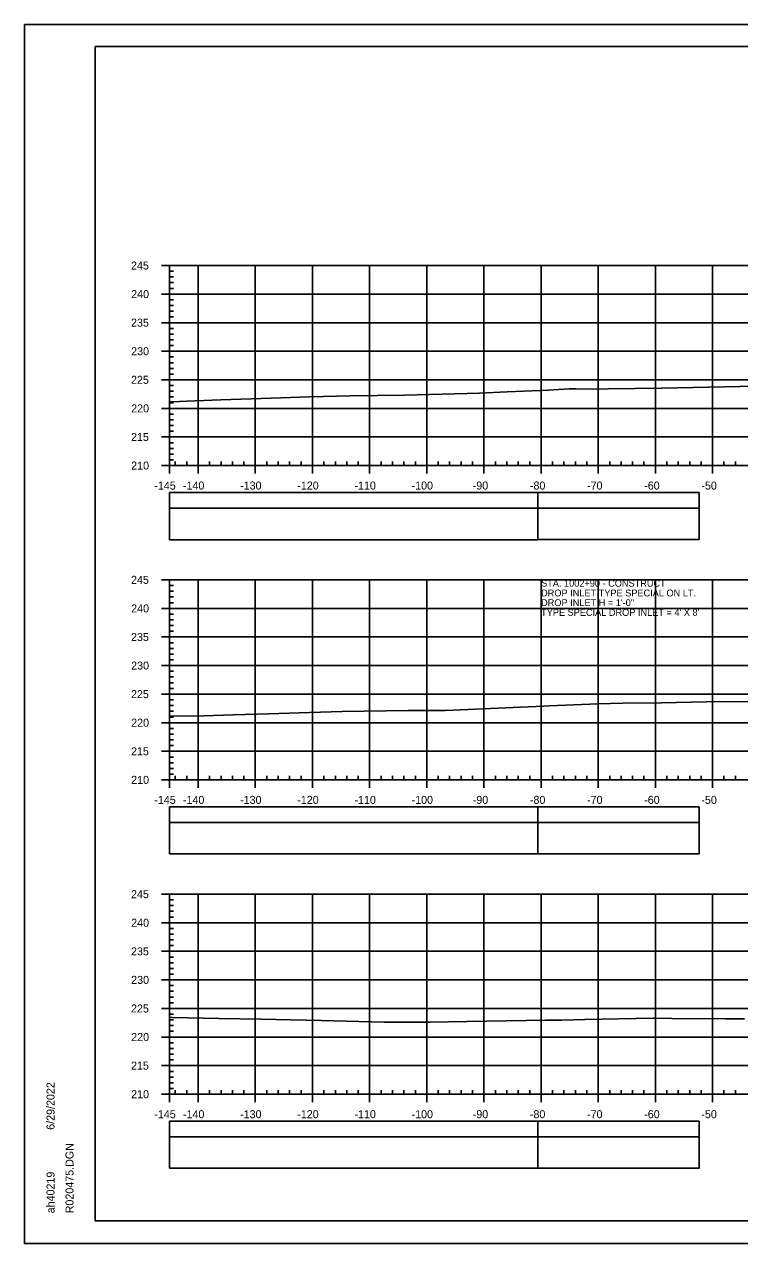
# Model space of a CAD drawing. Extents: x 1386544 to 1388153, y 379785 to 390999.
# Drawn here: x 1387207.5 to 1387332.7, y 379998.1 to 380211.5 of the extents above; entities that cross this region are included whole.
import ezdxf

# ---------------------------------------------------------------- set-up
doc = ezdxf.new("R2010")
doc.units = 0
for name, color, linetype in [('R_Axis', 7, 'Continuous'), ('R_Axis Annot', 7, 'Continuous'), ('R_Border', 7, 'Continuous'), ('R_Exist Surface', 7, 'Continuous'), ('R_Grid', 7, 'Continuous'), ('R_No Plot', 7, 'Continuous'), ('R_Striping', 7, 'Continuous'), ('R_Water Annot', 7, 'Continuous')]:
    doc.layers.add(name, color=color, linetype=linetype)

msp = doc.modelspace()

# ---------------------------------------------------------------- linework, layer by layer
at = {"layer": 'R_Axis'}
for p, q in [((1387231.55, 380169.28), (1387232.95, 380169.28)), ((1387232.95, 380134.28), (1387232.95, 380169.28)), ((1387232.95, 380168.28), (1387233.65, 380168.28)), ((1387232.95, 380167.28), (1387233.65, 380167.28)), ((1387232.95, 380166.28), (1387233.65, 380166.28)), ((1387231.55, 380164.28), (1387232.95, 380164.28)), ((1387232.95, 380165.28), (1387233.65, 380165.28)), ((1387232.95, 380163.28), (1387233.65, 380163.28)), ((1387232.95, 380162.28), (1387233.65, 380162.28)), ((1387232.95, 380161.28), (1387233.65, 380161.28)), ((1387231.55, 380159.28), (1387232.95, 380159.28)), ((1387232.95, 380160.28), (1387233.65, 380160.28)), ((1387232.95, 380158.28), (1387233.65, 380158.28)), ((1387232.95, 380157.28), (1387233.65, 380157.28)), ((1387232.95, 380156.28), (1387233.65, 380156.28)), ((1387232.95, 380155.28), (1387233.65, 380155.28)), ((1387231.55, 380154.28), (1387232.95, 380154.28)), ((1387232.95, 380153.28), (1387233.65, 380153.28)), ((1387232.95, 380152.28), (1387233.65, 380152.28)), ((1387232.95, 380151.28), (1387233.65, 380151.28)), ((1387231.55, 380149.28), (1387232.95, 380149.28)), ((1387232.95, 380150.28), (1387233.65, 380150.28)), ((1387232.95, 380148.28), (1387233.65, 380148.28)), ((1387232.95, 380147.28), (1387233.65, 380147.28)), ((1387232.95, 380146.28), (1387233.65, 380146.28)), ((1387231.55, 380144.28), (1387232.95, 380144.28)), ((1387232.95, 380145.28), (1387233.65, 380145.28)), ((1387232.95, 380143.28), (1387233.65, 380143.28)), ((1387232.95, 380142.28), (1387233.65, 380142.28)), ((1387232.95, 380141.28), (1387233.65, 380141.28)), ((1387232.95, 380140.28), (1387233.65, 380140.28)), ((1387231.55, 380139.28), (1387232.95, 380139.28)), ((1387232.95, 380138.28), (1387233.65, 380138.28)), ((1387232.95, 380137.28), (1387233.65, 380137.28)), ((1387232.95, 380136.28), (1387233.65, 380136.28)), ((1387231.55, 380134.28), (1387232.95, 380134.28)), ((1387232.95, 380135.28), (1387233.65, 380135.28)), ((1387232.95, 380134.28), (1387232.95, 380134.98)), ((1387232.95, 380134.28), (1387522.95, 380134.28)), ((1387232.95, 380132.88), (1387232.95, 380134.28)), ((1387233.95, 380134.28), (1387233.95, 380134.98)), ((1387235.95, 380134.28), (1387235.95, 380134.98)), ((1387237.95, 380132.88), (1387237.95, 380134.28)), ((1387239.95, 380134.28), (1387239.95, 380134.98)), ((1387241.95, 380134.28), (1387241.95, 380134.98)), ((1387243.95, 380134.28), (1387243.95, 380134.98)), ((1387245.95, 380134.28), (1387245.95, 380134.98)), ((1387247.95, 380132.88), (1387247.95, 380134.28)), ((1387249.95, 380134.28), (1387249.95, 380134.98)), ((1387251.95, 380134.28), (1387251.95, 380134.98)), ((1387253.95, 380134.28), (1387253.95, 380134.98)), ((1387255.95, 380134.28), (1387255.95, 380134.98)), ((1387257.95, 380132.88), (1387257.95, 380134.28)), ((1387259.95, 380134.28), (1387259.95, 380134.98)), ((1387261.95, 380134.28), (1387261.95, 380134.98)), ((1387263.95, 380134.28), (1387263.95, 380134.98)), ((1387265.95, 380134.28), (1387265.95, 380134.98)), ((1387267.95, 380132.88), (1387267.95, 380134.28)), ((1387269.95, 380134.28), (1387269.95, 380134.98)), ((1387271.95, 380134.28), (1387271.95, 380134.98)), ((1387273.95, 380134.28), (1387273.95, 380134.98)), ((1387275.95, 380134.28), (1387275.95, 380134.98)), ((1387277.95, 380132.88), (1387277.95, 380134.28)), ((1387279.95, 380134.28), (1387279.95, 380134.98)), ((1387281.95, 380134.28), (1387281.95, 380134.98)), ((1387283.95, 380134.28), (1387283.95, 380134.98)), ((1387285.95, 380134.28), (1387285.95, 380134.98)), ((1387287.95, 380132.88), (1387287.95, 380134.28)), ((1387289.95, 380134.28), (1387289.95, 380134.98)), ((1387291.95, 380134.28), (1387291.95, 380134.98)), ((1387293.95, 380134.28), (1387293.95, 380134.98)), ((1387295.95, 380134.28), (1387295.95, 380134.98)), ((1387297.95, 380132.88), (1387297.95, 380134.28)), ((1387299.95, 380134.28), (1387299.95, 380134.98)), ((1387301.95, 380134.28), (1387301.95, 380134.98)), ((1387303.95, 380134.28), (1387303.95, 380134.98)), ((1387305.95, 380134.28), (1387305.95, 380134.98)), ((1387307.95, 380132.88), (1387307.95, 380134.28)), ((1387309.95, 380134.28), (1387309.95, 380134.98)), ((1387311.95, 380134.28), (1387311.95, 380134.98)), ((1387313.95, 380134.28), (1387313.95, 380134.98)), ((1387315.95, 380134.28), (1387315.95, 380134.98)), ((1387317.95, 380132.88), (1387317.95, 380134.28)), ((1387319.95, 380134.28), (1387319.95, 380134.98)), ((1387321.95, 380134.28), (1387321.95, 380134.98)), ((1387323.95, 380134.28), (1387323.95, 380134.98)), ((1387325.95, 380134.28), (1387325.95, 380134.98)), ((1387327.95, 380132.88), (1387327.95, 380134.28)), ((1387329.95, 380134.28), (1387329.95, 380134.98)), ((1387331.95, 380134.28), (1387331.95, 380134.98)), ((1387231.55, 380114.28), (1387232.95, 380114.28)), ((1387232.95, 380079.28), (1387232.95, 380114.28)), ((1387232.95, 380113.28), (1387233.65, 380113.28)), ((1387232.95, 380112.28), (1387233.65, 380112.28)), ((1387232.95, 380111.28), (1387233.65, 380111.28)), ((1387232.95, 380110.28), (1387233.65, 380110.28)), ((1387231.55, 380109.28), (1387232.95, 380109.28)), ((1387232.95, 380108.28), (1387233.65, 380108.28)), ((1387232.95, 380107.28), (1387233.65, 380107.28)), ((1387232.95, 380106.28), (1387233.65, 380106.28)), ((1387231.55, 380104.28), (1387232.95, 380104.28)), ((1387232.95, 380105.28), (1387233.65, 380105.28)), ((1387232.95, 380103.28), (1387233.65, 380103.28)), ((1387232.95, 380102.28), (1387233.65, 380102.28)), ((1387232.95, 380101.28), (1387233.65, 380101.28)), ((1387232.95, 380100.28), (1387233.65, 380100.28)), ((1387231.55, 380099.28), (1387232.95, 380099.28)), ((1387232.95, 380098.28), (1387233.65, 380098.28)), ((1387232.95, 380097.28), (1387233.65, 380097.28)), ((1387232.95, 380096.28), (1387233.65, 380096.28)), ((1387232.95, 380095.28), (1387233.65, 380095.28)), ((1387231.55, 380094.28), (1387232.95, 380094.28)), ((1387232.95, 380093.28), (1387233.65, 380093.28)), ((1387232.95, 380092.28), (1387233.65, 380092.28)), ((1387232.95, 380091.28), (1387233.65, 380091.28)), ((1387231.55, 380089.28), (1387232.95, 380089.28)), ((1387232.95, 380090.28), (1387233.65, 380090.28)), ((1387232.95, 380088.28), (1387233.65, 380088.28)), ((1387232.95, 380087.28), (1387233.65, 380087.28)), ((1387232.95, 380086.28), (1387233.65, 380086.28)), ((1387232.95, 380085.28), (1387233.65, 380085.28)), ((1387231.55, 380084.28), (1387232.95, 380084.28)), ((1387232.95, 380083.28), (1387233.65, 380083.28)), ((1387232.95, 380082.28), (1387233.65, 380082.28)), ((1387232.95, 380081.28), (1387233.65, 380081.28)), ((1387232.95, 380080.28), (1387233.65, 380080.28)), ((1387231.55, 380079.28), (1387232.95, 380079.28)), ((1387232.95, 380079.28), (1387232.95, 380079.98)), ((1387232.95, 380079.28), (1387522.95, 380079.28)), ((1387232.95, 380077.88), (1387232.95, 380079.28)), ((1387233.95, 380079.28), (1387233.95, 380079.98)), ((1387235.95, 380079.28), (1387235.95, 380079.98)), ((1387237.95, 380077.88), (1387237.95, 380079.28)), ((1387239.95, 380079.28), (1387239.95, 380079.98)), ((1387241.95, 380079.28), (1387241.95, 380079.98)), ((1387243.95, 380079.28), (1387243.95, 380079.98)), ((1387245.95, 380079.28), (1387245.95, 380079.98)), ((1387247.95, 380077.88), (1387247.95, 380079.28)), ((1387249.95, 380079.28), (1387249.95, 380079.98)), ((1387251.95, 380079.28), (1387251.95, 380079.98)), ((1387253.95, 380079.28), (1387253.95, 380079.98)), ((1387255.95, 380079.28), (1387255.95, 380079.98)), ((1387257.95, 380077.88), (1387257.95, 380079.28)), ((1387259.95, 380079.28), (1387259.95, 380079.98)), ((1387261.95, 380079.28), (1387261.95, 380079.98)), ((1387263.95, 380079.28), (1387263.95, 380079.98)), ((1387265.95, 380079.28), (1387265.95, 380079.98)), ((1387267.95, 380077.88), (1387267.95, 380079.28)), ((1387269.95, 380079.28), (1387269.95, 380079.98)), ((1387271.95, 380079.28), (1387271.95, 380079.98)), ((1387273.95, 380079.28), (1387273.95, 380079.98)), ((1387275.95, 380079.28), (1387275.95, 380079.98)), ((1387277.95, 380077.88), (1387277.95, 380079.28)), ((1387279.95, 380079.28), (1387279.95, 380079.98)), ((1387281.95, 380079.28), (1387281.95, 380079.98)), ((1387283.95, 380079.28), (1387283.95, 380079.98)), ((1387285.95, 380079.28), (1387285.95, 380079.98)), ((1387287.95, 380077.88), (1387287.95, 380079.28)), ((1387289.95, 380079.28), (1387289.95, 380079.98)), ((1387291.95, 380079.28), (1387291.95, 380079.98)), ((1387293.95, 380079.28), (1387293.95, 380079.98)), ((1387295.95, 380079.28), (1387295.95, 380079.98)), ((1387297.95, 380077.88), (1387297.95, 380079.28)), ((1387299.95, 380079.28), (1387299.95, 380079.98)), ((1387301.95, 380079.28), (1387301.95, 380079.98)), ((1387303.95, 380079.28), (1387303.95, 380079.98)), ((1387305.95, 380079.28), (1387305.95, 380079.98)), ((1387307.95, 380077.88), (1387307.95, 380079.28)), ((1387309.95, 380079.28), (1387309.95, 380079.98)), ((1387311.95, 380079.28), (1387311.95, 380079.98)), ((1387313.95, 380079.28), (1387313.95, 380079.98)), ((1387315.95, 380079.28), (1387315.95, 380079.98)), ((1387317.95, 380077.88), (1387317.95, 380079.28)), ((1387319.95, 380079.28), (1387319.95, 380079.98)), ((1387321.95, 380079.28), (1387321.95, 380079.98)), ((1387323.95, 380079.28), (1387323.95, 380079.98)), ((1387325.95, 380079.28), (1387325.95, 380079.98)), ((1387327.95, 380077.88), (1387327.95, 380079.28)), ((1387329.95, 380079.28), (1387329.95, 380079.98)), ((1387331.95, 380079.28), (1387331.95, 380079.98)), ((1387231.55, 380059.28), (1387232.95, 380059.28)), ((1387232.95, 380024.28), (1387232.95, 380059.28)), ((1387232.95, 380058.28), (1387233.65, 380058.28)), ((1387232.95, 380057.28), (1387233.65, 380057.28)), ((1387232.95, 380056.28), (1387233.65, 380056.28)), ((1387232.95, 380055.28), (1387233.65, 380055.28)), ((1387231.55, 380054.28), (1387232.95, 380054.28)), ((1387232.95, 380053.28), (1387233.65, 380053.28)), ((1387232.95, 380052.28), (1387233.65, 380052.28)), ((1387232.95, 380051.28), (1387233.65, 380051.28)), ((1387232.95, 380050.28), (1387233.65, 380050.28)), ((1387231.55, 380049.28), (1387232.95, 380049.28)), ((1387232.95, 380048.28), (1387233.65, 380048.28)), ((1387232.95, 380047.28), (1387233.65, 380047.28)), ((1387232.95, 380046.28), (1387233.65, 380046.28)), ((1387231.55, 380044.28), (1387232.95, 380044.28)), ((1387232.95, 380045.28), (1387233.65, 380045.28)), ((1387232.95, 380043.28), (1387233.65, 380043.28)), ((1387232.95, 380042.28), (1387233.65, 380042.28)), ((1387232.95, 380041.28), (1387233.65, 380041.28)), ((1387232.95, 380040.28), (1387233.65, 380040.28)), ((1387231.55, 380039.28), (1387232.95, 380039.28)), ((1387232.95, 380038.28), (1387233.65, 380038.28)), ((1387232.95, 380037.28), (1387233.65, 380037.28)), ((1387232.95, 380036.28), (1387233.65, 380036.28)), ((1387231.55, 380034.28), (1387232.95, 380034.28)), ((1387232.95, 380035.28), (1387233.65, 380035.28)), ((1387232.95, 380033.28), (1387233.65, 380033.28)), ((1387232.95, 380032.28), (1387233.65, 380032.28)), ((1387232.95, 380031.28), (1387233.65, 380031.28)), ((1387231.55, 380029.28), (1387232.95, 380029.28)), ((1387232.95, 380030.28), (1387233.65, 380030.28)), ((1387232.95, 380028.28), (1387233.65, 380028.28)), ((1387232.95, 380027.28), (1387233.65, 380027.28)), ((1387232.95, 380026.28), (1387233.65, 380026.28)), ((1387232.95, 380025.28), (1387233.65, 380025.28)), ((1387232.95, 380024.28), (1387232.95, 380024.98)), ((1387233.95, 380024.28), (1387233.95, 380024.98)), ((1387235.95, 380024.28), (1387235.95, 380024.98)), ((1387239.95, 380024.28), (1387239.95, 380024.98)), ((1387241.95, 380024.28), (1387241.95, 380024.98)), ((1387243.95, 380024.28), (1387243.95, 380024.98)), ((1387245.95, 380024.28), (1387245.95, 380024.98)), ((1387249.95, 380024.28), (1387249.95, 380024.98)), ((1387251.95, 380024.28), (1387251.95, 380024.98)), ((1387253.95, 380024.28), (1387253.95, 380024.98)), ((1387255.95, 380024.28), (1387255.95, 380024.98)), ((1387259.95, 380024.28), (1387259.95, 380024.98)), ((1387261.95, 380024.28), (1387261.95, 380024.98)), ((1387263.95, 380024.28), (1387263.95, 380024.98)), ((1387265.95, 380024.28), (1387265.95, 380024.98)), ((1387269.95, 380024.28), (1387269.95, 380024.98)), ((1387271.95, 380024.28), (1387271.95, 380024.98)), ((1387273.95, 380024.28), (1387273.95, 380024.98)), ((1387275.95, 380024.28), (1387275.95, 380024.98)), ((1387279.95, 380024.28), (1387279.95, 380024.98)), ((1387281.95, 380024.28), (1387281.95, 380024.98)), ((1387283.95, 380024.28), (1387283.95, 380024.98)), ((1387285.95, 380024.28), (1387285.95, 380024.98)), ((1387289.95, 380024.28), (1387289.95, 380024.98)), ((1387291.95, 380024.28), (1387291.95, 380024.98)), ((1387293.95, 380024.28), (1387293.95, 380024.98)), ((1387295.95, 380024.28), (1387295.95, 380024.98)), ((1387299.95, 380024.28), (1387299.95, 380024.98)), ((1387301.95, 380024.28), (1387301.95, 380024.98)), ((1387303.95, 380024.28), (1387303.95, 380024.98)), ((1387305.95, 380024.28), (1387305.95, 380024.98)), ((1387309.95, 380024.28), (1387309.95, 380024.98)), ((1387311.95, 380024.28), (1387311.95, 380024.98)), ((1387313.95, 380024.28), (1387313.95, 380024.98)), ((1387315.95, 380024.28), (1387315.95, 380024.98)), ((1387319.95, 380024.28), (1387319.95, 380024.98)), ((1387321.95, 380024.28), (1387321.95, 380024.98)), ((1387323.95, 380024.28), (1387323.95, 380024.98)), ((1387325.95, 380024.28), (1387325.95, 380024.98)), ((1387329.95, 380024.28), (1387329.95, 380024.98)), ((1387331.95, 380024.28), (1387331.95, 380024.98)), ((1387231.55, 380024.28), (1387232.95, 380024.28)), ((1387232.95, 380024.28), (1387522.95, 380024.28)), ((1387232.95, 380022.88), (1387232.95, 380024.28)), ((1387237.95, 380022.88), (1387237.95, 380024.28)), ((1387247.95, 380022.88), (1387247.95, 380024.28)), ((1387257.95, 380022.88), (1387257.95, 380024.28)), ((1387267.95, 380022.88), (1387267.95, 380024.28)), ((1387277.95, 380022.88), (1387277.95, 380024.28)), ((1387287.95, 380022.88), (1387287.95, 380024.28)), ((1387297.95, 380022.88), (1387297.95, 380024.28)), ((1387307.95, 380022.88), (1387307.95, 380024.28)), ((1387317.95, 380022.88), (1387317.95, 380024.28)), ((1387327.95, 380022.88), (1387327.95, 380024.28))]:
    msp.add_line(p, q, dxfattribs=at)
at = {"layer": 'R_Axis Annot'}
for points in [[(1387232.95, 380126.84), (1387297.39, 380126.84), (1387297.39, 380129.55), (1387232.95, 380129.55)], [(1387232.95, 380121.31), (1387297.39, 380121.31), (1387297.39, 380126.84), (1387232.95, 380126.84)], [(1387232.95, 380071.84), (1387297.39, 380071.84), (1387297.39, 380074.55), (1387232.95, 380074.55)], [(1387232.95, 380066.31), (1387297.39, 380066.31), (1387297.39, 380071.84), (1387232.95, 380071.84)], [(1387232.95, 380016.84), (1387297.39, 380016.84), (1387297.39, 380019.55), (1387232.95, 380019.55)], [(1387232.95, 380011.31), (1387297.39, 380011.31), (1387297.39, 380016.84), (1387232.95, 380016.84)]]:
    msp.add_lwpolyline(points, close=True, dxfattribs=at)
at = {"layer": 'R_Border'}
for p, q in [((1387219.95, 380207.58), (1387536.13, 380207.58)), ((1387219.95, 380002.12), (1387219.95, 380207.58)), ((1387219.95, 380002.12), (1387219.95, 380002.12)), ((1387536.13, 380002.12), (1387219.95, 380002.12))]:
    msp.add_line(p, q, dxfattribs=at)
at = {"layer": 'R_Exist Surface'}
for points in [[(1387232.95, 380145.44), (1387233.3, 380145.45), (1387237.4, 380145.61), (1387241.92, 380145.77), (1387250.73, 380146.09), (1387257.41, 380146.28), (1387264.54, 380146.46), (1387274.03, 380146.6), (1387287.18, 380146.92), (1387292, 380147.16), (1387294.89, 380147.27), (1387299.22, 380147.48), (1387302.89, 380147.7), (1387304.01, 380147.68), (1387305, 380147.67), (1387318.99, 380147.82), (1387338.31, 380148.22)], [(1387232.95, 380090.4), (1387238.95, 380090.47), (1387244.07, 380090.66), (1387250.23, 380090.83), (1387257.45, 380091.06), (1387263.13, 380091.23), (1387274.69, 380091.4), (1387281.21, 380091.43), (1387294.37, 380092), (1387298.42, 380092.15), (1387299.43, 380092.22), (1387307.9, 380092.57), (1387312.23, 380092.69), (1387319, 380092.76), (1387326.85, 380092.93), (1387337.94, 380093.02)], [(1387232.95, 380037.74), (1387233.41, 380037.72), (1387241.61, 380037.55), (1387248.92, 380037.38), (1387259.45, 380037.17), (1387270.52, 380036.86), (1387278.09, 380036.88), (1387278.52, 380036.88), (1387285.03, 380037.02), (1387295.3, 380037.2), (1387298.71, 380037.23), (1387301.55, 380037.25), (1387305.63, 380037.33), (1387317.53, 380037.57), (1387317.67, 380037.57), (1387320.81, 380037.52), (1387330.23, 380037.46), (1387333.54, 380037.47)]]:
    msp.add_lwpolyline(points, dxfattribs=at)
at = {"layer": 'R_Grid'}
for p, q in [((1387232.95, 380169.28), (1387522.95, 380169.28)), ((1387232.95, 380134.28), (1387232.95, 380169.28)), ((1387237.95, 380134.28), (1387237.95, 380169.28)), ((1387247.95, 380134.28), (1387247.95, 380169.28)), ((1387257.95, 380134.28), (1387257.95, 380169.28)), ((1387267.95, 380134.28), (1387267.95, 380169.28)), ((1387277.95, 380134.28), (1387277.95, 380169.28)), ((1387287.95, 380134.28), (1387287.95, 380169.28)), ((1387297.95, 380134.28), (1387297.95, 380169.28)), ((1387307.95, 380134.28), (1387307.95, 380169.28)), ((1387317.95, 380134.28), (1387317.95, 380169.28)), ((1387327.95, 380134.28), (1387327.95, 380169.28)), ((1387232.95, 380164.28), (1387522.95, 380164.28)), ((1387232.95, 380159.28), (1387522.95, 380159.28)), ((1387232.95, 380154.28), (1387522.95, 380154.28)), ((1387232.95, 380149.28), (1387522.95, 380149.28)), ((1387232.95, 380144.28), (1387522.95, 380144.28)), ((1387232.95, 380139.28), (1387522.95, 380139.28)), ((1387232.95, 380134.28), (1387522.95, 380134.28)), ((1387232.95, 380114.28), (1387522.95, 380114.28)), ((1387232.95, 380079.28), (1387232.95, 380114.28)), ((1387237.95, 380079.28), (1387237.95, 380114.28)), ((1387247.95, 380079.28), (1387247.95, 380114.28)), ((1387257.95, 380079.28), (1387257.95, 380114.28)), ((1387267.95, 380079.28), (1387267.95, 380114.28)), ((1387277.95, 380079.28), (1387277.95, 380114.28)), ((1387287.95, 380079.28), (1387287.95, 380114.28)), ((1387297.95, 380079.28), (1387297.95, 380114.28)), ((1387307.95, 380079.28), (1387307.95, 380114.28)), ((1387317.95, 380079.28), (1387317.95, 380114.28)), ((1387327.95, 380079.28), (1387327.95, 380114.28)), ((1387232.95, 380109.28), (1387522.95, 380109.28)), ((1387232.95, 380104.28), (1387522.95, 380104.28)), ((1387232.95, 380099.28), (1387522.95, 380099.28)), ((1387232.95, 380094.28), (1387522.95, 380094.28)), ((1387232.95, 380089.28), (1387522.95, 380089.28)), ((1387232.95, 380084.28), (1387522.95, 380084.28)), ((1387232.95, 380079.28), (1387522.95, 380079.28)), ((1387232.95, 380059.28), (1387522.95, 380059.28)), ((1387232.95, 380024.28), (1387232.95, 380059.28)), ((1387237.95, 380024.28), (1387237.95, 380059.28)), ((1387247.95, 380024.28), (1387247.95, 380059.28)), ((1387257.95, 380024.28), (1387257.95, 380059.28)), ((1387267.95, 380024.28), (1387267.95, 380059.28)), ((1387277.95, 380024.28), (1387277.95, 380059.28)), ((1387287.95, 380024.28), (1387287.95, 380059.28)), ((1387297.95, 380024.28), (1387297.95, 380059.28)), ((1387307.95, 380024.28), (1387307.95, 380059.28)), ((1387317.95, 380024.28), (1387317.95, 380059.28)), ((1387327.95, 380024.28), (1387327.95, 380059.28)), ((1387232.95, 380054.28), (1387522.95, 380054.28)), ((1387232.95, 380049.28), (1387522.95, 380049.28)), ((1387232.95, 380044.28), (1387522.95, 380044.28)), ((1387232.95, 380039.28), (1387522.95, 380039.28)), ((1387232.95, 380034.28), (1387522.95, 380034.28)), ((1387232.95, 380029.28), (1387522.95, 380029.28)), ((1387232.95, 380024.28), (1387522.95, 380024.28))]:
    msp.add_line(p, q, dxfattribs=at)
at = {"layer": 'R_No Plot'}
for p, q in [((1387207.55, 380211.47), (1387540.89, 380211.47)), ((1387207.55, 379998.14), (1387540.89, 379998.14))]:
    msp.add_line(p, q, dxfattribs=at)
for points in [[(1387207.55, 380211.47), (1387540.89, 380211.47), (1387540.89, 379998.14), (1387207.55, 379998.14)], [(1387453.87, 380207.58), (1387473.49, 380207.58), (1387473.49, 380197.7), (1387489.6, 380197.7), (1387512.8, 380197.7), (1387512.8, 380173.37), (1387536.13, 380173.37), (1387536.13, 380002.12), (1387219.95, 380002.12), (1387219.95, 380207.58)]]:
    msp.add_lwpolyline(points, close=True, dxfattribs=at)
at = {"layer": 'R_Striping'}
for points in [[(1387297.39, 380126.84), (1387325.58, 380126.84), (1387325.58, 380129.55), (1387297.39, 380129.55)], [(1387297.39, 380121.32), (1387325.58, 380121.32), (1387325.58, 380126.84), (1387297.39, 380126.84)], [(1387297.39, 380071.84), (1387325.58, 380071.84), (1387325.58, 380074.55), (1387297.39, 380074.55)], [(1387297.39, 380066.32), (1387325.58, 380066.32), (1387325.58, 380071.84), (1387297.39, 380071.84)], [(1387297.39, 380016.84), (1387325.58, 380016.84), (1387325.58, 380019.55), (1387297.39, 380019.55)], [(1387297.39, 380011.32), (1387325.58, 380011.32), (1387325.58, 380016.84), (1387297.39, 380016.84)]]:
    msp.add_lwpolyline(points, close=True, dxfattribs=at)

# ---------------------------------------------------------------- texts
at = {"layer": 'R_Axis Annot'}
for s, p in [('245', (1387226.2, 380168.58)), ('240', (1387226.23, 380163.58)), ('235', (1387226.2, 380158.58)), ('230', (1387226.23, 380153.58)), ('225', (1387226.2, 380148.58)), ('220', (1387226.23, 380143.58)), ('215', (1387226.2, 380138.58)), ('210', (1387226.23, 380133.58)), ('-145', (1387230.28, 380130.08)), ('-140', (1387235.29, 380130.08)), ('-130', (1387245.29, 380130.08)), ('-120', (1387255.29, 380130.08)), ('-110', (1387265.29, 380130.08)), ('-100', (1387275.29, 380130.08)), ('-90', (1387285.99, 380130.08)), ('-80', (1387295.99, 380130.08)), ('-70', (1387305.99, 380130.08)), ('-60', (1387315.99, 380130.08)), ('-50', (1387325.99, 380130.08)), ('245', (1387226.2, 380113.58)), ('240', (1387226.23, 380108.58)), ('235', (1387226.2, 380103.58)), ('230', (1387226.23, 380098.58)), ('225', (1387226.2, 380093.58)), ('220', (1387226.23, 380088.58)), ('215', (1387226.2, 380083.58)), ('210', (1387226.23, 380078.58)), ('-145', (1387230.28, 380075.08)), ('-140', (1387235.29, 380075.08)), ('-130', (1387245.29, 380075.08)), ('-120', (1387255.29, 380075.08)), ('-110', (1387265.29, 380075.08)), ('-100', (1387275.29, 380075.08)), ('-90', (1387285.99, 380075.08)), ('-80', (1387295.99, 380075.08)), ('-70', (1387305.99, 380075.08)), ('-60', (1387315.99, 380075.08)), ('-50', (1387325.99, 380075.08)), ('245', (1387226.2, 380058.58)), ('240', (1387226.23, 380053.58)), ('235', (1387226.2, 380048.58)), ('230', (1387226.23, 380043.58)), ('225', (1387226.2, 380038.58)), ('220', (1387226.23, 380033.58)), ('215', (1387226.2, 380028.58)), ('210', (1387226.23, 380023.58)), ('-145', (1387230.28, 380020.08)), ('-140', (1387235.29, 380020.08)), ('-130', (1387245.29, 380020.08)), ('-120', (1387255.29, 380020.08)), ('-110', (1387265.29, 380020.08)), ('-100', (1387275.29, 380020.08)), ('-90', (1387285.99, 380020.08)), ('-80', (1387295.99, 380020.08)), ('-70', (1387305.99, 380020.08)), ('-60', (1387315.99, 380020.08)), ('-50', (1387325.99, 380020.08))]:
    msp.add_text(s, height=1.4, dxfattribs=at).set_placement(p)
at = {"layer": 'R_Border'}
for s, p in [('6/29/2022', (1387212.82, 380018.05)), ('R020475.DGN', (1387216.14, 380003.44)), ('ah40219', (1387212.82, 380003.44))]:
    msp.add_text(s, height=1.4, rotation=90, dxfattribs=at).set_placement(p)
at = {"layer": 'R_Water Annot'}
for s, p in [('STA. 1002+90 - CONSTRUCT', (1387297.95, 380113.08)), ('DROP INLET TYPE SPECIAL ON LT.', (1387297.95, 380111.38)), ('DROP INLET H = 1\'-0"', (1387297.95, 380109.68)), ("TYPE SPECIAL DROP INLET = 4' X 8'", (1387297.95, 380107.98))]:
    msp.add_text(s, height=1.2, dxfattribs=at).set_placement(p)

doc.saveas('drawing.dxf')
